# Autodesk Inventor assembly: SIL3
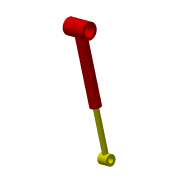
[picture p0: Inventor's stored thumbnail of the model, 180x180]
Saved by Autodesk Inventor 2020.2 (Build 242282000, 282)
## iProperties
Manager: www.cadconsulting.pl
Company: Fabian Stasiak CAD Consulting
Created: 2005-10
Part Number: SIL3
Document SubType Name: Assembly
Designer: F.Stasiak
Author: F.Stasiak
Subject: Zbiór ćwiczeń. Autodesk Inventor 2020. Kurs podstawowy
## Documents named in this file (3)
- C:\2020_Kurs_podstawowy\R6 Zespoły\Lustro\SIL3.iam
- C:\2020_Kurs_podstawowy\R6 Zespoły\Lustro\Cyl3.ipt
- C:\2020_Kurs_podstawowy\R6 Zespoły\Lustro\T3.ipt
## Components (2 placed, 2 different names)
1. Cyl3:1
2. T3:1
